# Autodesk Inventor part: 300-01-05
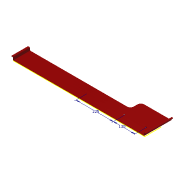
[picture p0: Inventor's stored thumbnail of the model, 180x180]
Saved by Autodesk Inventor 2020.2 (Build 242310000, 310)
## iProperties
Created: 2014-10
Part Number: 300-01-05
Material: Stal
Document SubType Name: Konstrukcja blachowa
Designer: F.Stasiak
Density: 7.85 g/cm^3
Appearance: Czerwona
Sheet Metal Rule: Domyślny_mm
Catalog Web Link: www.expertbooks.pl
Manager: www.cadconsulting.pl
Company: Fabian Stasiak CAD Consulting
Author: F.Stasiak
Subject: Zbiór ćwiczeń. Autodesk Inventor 2020. Kurs Professional
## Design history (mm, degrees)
sketch "Szkic1"
  geometry: L1 (-396, 50)-(396, 50); L2 (396, 50)-(396, -50); L3 (396, -50)-(-396, -50); L4 (-396, -50)-(-396, 50); L5 (-396, 50)-(396, -50); L6 (396, 50)-(-396, -50); 1 further point
  constraints: 12 end point, 2 midpoint, 2 parallel, 1 horizontal, 1 perpendicular
  dimensions: "d0" = 792 distance of L2.end L3.end; "d1" = 100 distance of L1.end L2.end
extrude "Wyciągnięcie proste1" new body sketch "Szkic1" distance "d2" = 3; taper "d3" = 0 deg
sketch "Szkic2"
  geometry: L1 (-396, -50)-(-396, 50) reference; L2 (-396, -50)-(396, -50) reference; 3 further points
  constraints: 2 horizontal alignment
  dimensions: "d55" = 225 distance of point (0, 0) point (-225, 0); "d63" = 130 distance of point (-225, 0) point (-355, 0)
node "Kołnierz1"
node "Kołnierz2"
node "Kołnierz3"
node "Kołnierz4"
hole "Otwór1" sketch "Szkic2" diameter "d56" = 8; stored, may be unused: countersink angle "d60" = 90 deg, drill point angle "d62" = 118 deg; dims "d57" = 6, "d58" = 4, "d59" = 2, "d61" = 3 (= Grubość)
hole "Otwór2" sketch "Szkic2" diameter "d65" = 8; stored, may be unused: countersink angle "d69" = 90 deg, drill point angle "d71" = 118 deg; dims "d66" = 6, "d67" = 4, "d68" = 2, "d70" = 3 (= Grubość)
sketch "Szkic9"
  geometry: L1 (780, -3)-(780, 0) reference; L2 (0, 0)-(780, 0) reference; L3 (0, 0)-(0, -3) reference; L4 (780, -3)-(0, -3) reference; L5 (786, -6)-(783, -6) reference; L6 (780, -3)-(780, 0) reference; L7 (783, -14)-(786, -14) reference; L8 (786, -14)-(786, -6) reference; L9 (786, -6)-(783, -6) reference; L10 (783, -14)-(783, -6) reference; L11 (789, -17)-(789, -20) reference; L12 (783, -14)-(786, -14) reference; L13 (789, -17)-(789, -20) reference; L14 (789, -20)-(795, -20) reference; L15 (795, -17)-(795, -20) reference; L16 (795, -17)-(789, -17) reference; L17 (601, 0)-(601, -3); A1 r 6 centre (780, -6) between (786, -6) and (780, 0) reference; A2 r 3 centre (780, -6) between (783, -6) and (780, -3) reference; A3 r 3 centre (789, -14) between (786, -14) and (789, -17) reference; A4 r 6 centre (789, -14) between (783, -14) and (789, -20) reference; 1 further point
  constraints: 2 end point, 2 point on line, 1 perpendicular
  dimensions: "d72" = 185 distance between parallel lines of L8 L17
extrude "Wyciągnięcie proste4" join sketch "Szkic9" distance "d73" = 63; taper "d74" = 0 deg
feature "Zaokrąglenie narożnika1" dims "d75" = 20
node "Bryła1"
sketch "Szkic5"
  geometry: L1 through (0, 0) direction (0, 1); L2 (0, 20)-(-100, 20); L3 (-100, 20)-(-100, 0); 1 other entity
  constraints: 5 end point, 2 vertical, 2 other
feature "Płyta1" dims "d15" = 3 (= SzerokośćGięciaPodcięcia), "d16" = 1.5 (= GłębokośćGięciaPodcięcia), "d17" = 6 (= MinimalnaPozostałość), "d18" = 3 (= PromieńGięcia), "d19" = 20, "d20" = 90 deg, "d21" = 3 (= PromieńGięcia), "d22" = 12 (= RozmiarPodcięciaNarożnika), "d23" = 3 (= Wielk_odstępu), "d24" = 3 (= Rozmiar_promienia_Jacobiego), "d76" = 3 (= Grubość), "OdstępPołączenia" = 0.01
feature "Gięcie1" dims "d15" = 3 (= SzerokośćGięciaPodcięcia), "d16" = 1.5 (= GłębokośćGięciaPodcięcia), "d17" = 6 (= MinimalnaPozostałość), "d18" = 3 (= PromieńGięcia), "d19" = 20, "d20" = 90 deg, "d21" = 3 (= PromieńGięcia), "d76" = 3 (= Grubość), "OdstępPołączenia" = 0.01
feature "Narożnik1" dims "d19" = 20, "d20" = 90 deg, "d22" = 12 (= RozmiarPodcięciaNarożnika), "d23" = 3 (= Wielk_odstępu), "d24" = 3 (= Rozmiar_promienia_Jacobiego)
sketch "Szkic6"
  geometry: L1 (-12, 0)-(-12, -100); L2 (-12, -100)-(0, -100); 1 other entity
  constraints: 4 end point, 4 other
feature "Płyta2" dims "d25" = 3 (= SzerokośćGięciaPodcięcia), "d26" = 1.5 (= GłębokośćGięciaPodcięcia), "d27" = 6 (= MinimalnaPozostałość), "d28" = 3 (= PromieńGięcia), "d29" = 12, "d30" = 90 deg, "d31" = 3 (= PromieńGięcia), "d32" = 12 (= RozmiarPodcięciaNarożnika), "d33" = 3 (= Wielk_odstępu), "d34" = 3 (= Rozmiar_promienia_Jacobiego), "d76" = 3 (= Grubość), "OdstępPołączenia" = 0.01
feature "Gięcie2" dims "d25" = 3 (= SzerokośćGięciaPodcięcia), "d26" = 1.5 (= GłębokośćGięciaPodcięcia), "d27" = 6 (= MinimalnaPozostałość), "d28" = 3 (= PromieńGięcia), "d29" = 12, "d30" = 90 deg, "d31" = 3 (= PromieńGięcia), "d76" = 3 (= Grubość), "OdstępPołączenia" = 0.01
feature "Narożnik2" dims "d29" = 12, "d30" = 90 deg, "d32" = 12 (= RozmiarPodcięciaNarożnika), "d33" = 3 (= Wielk_odstępu), "d34" = 3 (= Rozmiar_promienia_Jacobiego)
sketch "Szkic7"
  geometry: L1 through (0, 0) direction (0, 1); L2 (0, 20)-(-100, 20); L3 (-100, 20)-(-100, 0); 1 other entity
  constraints: 5 end point, 2 vertical, 2 other
feature "Płyta3" dims "d35" = 3 (= SzerokośćGięciaPodcięcia), "d36" = 1.5 (= GłębokośćGięciaPodcięcia), "d37" = 6 (= MinimalnaPozostałość), "d38" = 3 (= PromieńGięcia), "d39" = 20, "d40" = 90 deg, "d41" = 3 (= PromieńGięcia), "d42" = 12 (= RozmiarPodcięciaNarożnika), "d43" = 3 (= Wielk_odstępu), "d44" = 3 (= Rozmiar_promienia_Jacobiego), "d76" = 3 (= Grubość), "OdstępPołączenia" = 0.01
feature "Gięcie3" dims "d35" = 3 (= SzerokośćGięciaPodcięcia), "d36" = 1.5 (= GłębokośćGięciaPodcięcia), "d37" = 6 (= MinimalnaPozostałość), "d38" = 3 (= PromieńGięcia), "d39" = 20, "d40" = 90 deg, "d41" = 3 (= PromieńGięcia), "d76" = 3 (= Grubość), "OdstępPołączenia" = 0.01
feature "Narożnik3" dims "d39" = 20, "d40" = 90 deg, "d42" = 12 (= RozmiarPodcięciaNarożnika), "d43" = 3 (= Wielk_odstępu), "d44" = 3 (= Rozmiar_promienia_Jacobiego)
sketch "Szkic8"
  geometry: L1 (12, 0)-(12, 100); L2 (12, 100)-(0, 100); 1 other entity
  constraints: 4 end point, 4 other
feature "Płyta4" dims "d45" = 3 (= SzerokośćGięciaPodcięcia), "d46" = 1.5 (= GłębokośćGięciaPodcięcia), "d47" = 6 (= MinimalnaPozostałość), "d48" = 3 (= PromieńGięcia), "d49" = 12, "d50" = 90 deg, "d51" = 3 (= PromieńGięcia), "d52" = 12 (= RozmiarPodcięciaNarożnika), "d53" = 3 (= Wielk_odstępu), "d54" = 3 (= Rozmiar_promienia_Jacobiego), "d76" = 3 (= Grubość), "OdstępPołączenia" = 0.01
feature "Gięcie4" dims "d45" = 3 (= SzerokośćGięciaPodcięcia), "d46" = 1.5 (= GłębokośćGięciaPodcięcia), "d47" = 6 (= MinimalnaPozostałość), "d48" = 3 (= PromieńGięcia), "d49" = 12, "d50" = 90 deg, "d51" = 3 (= PromieńGięcia), "d76" = 3 (= Grubość), "OdstępPołączenia" = 0.01
feature "Narożnik4" dims "d49" = 12, "d50" = 90 deg, "d52" = 12 (= RozmiarPodcięciaNarożnika), "d53" = 3 (= Wielk_odstępu), "d54" = 3 (= Rozmiar_promienia_Jacobiego)
node "Pętla rzutowana1"
node "Pętla rzutowana2"
node "Pętla rzutowana3"
node "Pętla rzutowana4"
node "Pętla rzutowana5"
other parameters: "Grubość" = 3 (derived), "WspółczynnikK" = 4.4, "PromieńGięcia" = 3 (= Grubość), "SzerokośćGięciaPodcięcia" = 3 (= Grubość), "GłębokośćGięciaPodcięcia" = 1.5 (= 0.5 x Grubość), "RozmiarPodcięciaNarożnika" = 12 (= 4 x Grubość), "MinimalnaPozostałość" = 6 (= 2 x Grubość), "PromieńPrzejścia" = 3 (= PromieńGięcia), "Rozmiar_promienia_Jacobiego" = 3 (= PromieńGięcia), "Wielk_odstępu" = 3 (= Grubość)
